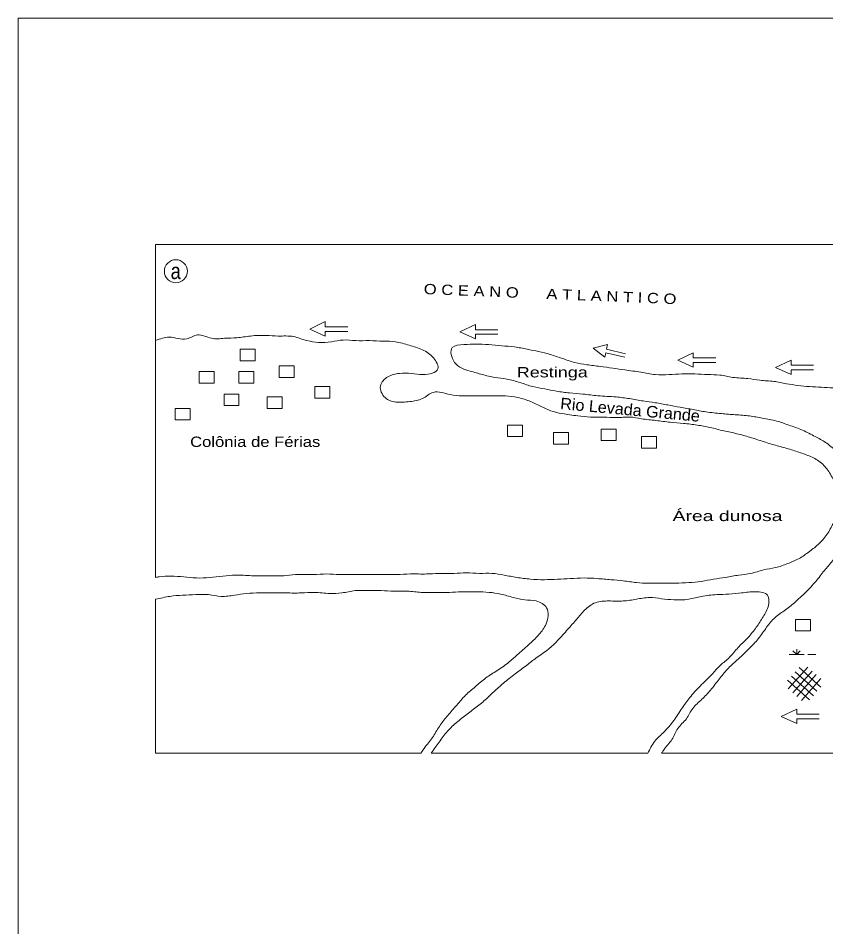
# Model space of a CAD drawing. Extents: x -4.1 to 18.6, y -18.7 to 13.4.
# Drawn here: x -4.12 to 9.93, y -2.41 to 13.4 of the extents above; entities that cross this region are included whole.
import ezdxf
from ezdxf.enums import TextEntityAlignment as Align

# ---------------------------------------------------------------- set-up
doc = ezdxf.new("R2010")
doc.units = 0
doc.header["$LTSCALE"] = 0.072
doc.layers.add('1', color=7, linetype='Continuous', lineweight=13)
doc.layers.add('3', color=7, linetype='Continuous', lineweight=13)

msp = doc.modelspace()

# ---------------------------------------------------------------- linework, layer by layer
at = {"layer": '1'}
for p, q in [((-1.73, 8.24), (-1.73, 7.79)), ((9.27, 1.73), (9.61, 2.11)), ((9.84, 1.76), (9.46, 2.1)), ((9.71, 1.61), (9.33, 1.95)), ((9.35, 1.66), (9.69, 2.04)), ((9.77, 1.69), (9.39, 2.03)), ((9.42, 1.6), (9.76, 1.98)), ((9.5, 1.53), (9.84, 1.91)), ((9.64, 1.54), (9.26, 1.88)), ((3.06, 0.61), (6.83, 0.61))]:
    msp.add_line(p, q, dxfattribs=at)
for points in [[(18.56, -18.67), (18.56, 13.4), (-4.12, 13.4), (-4.12, -18.67)], [(-0.26, 7.64), (0, 7.64), (0, 7.44), (-0.26, 7.44)], [(0.42, 7.35), (0.68, 7.35), (0.68, 7.15), (0.42, 7.15)], [(-0.97, 7.25), (-0.71, 7.25), (-0.71, 7.05), (-0.97, 7.05)], [(-0.28, 7.25), (-0.02, 7.25), (-0.02, 7.05), (-0.28, 7.05)], [(1.04, 6.99), (1.3, 6.99), (1.3, 6.79), (1.04, 6.79)], [(-0.54, 6.86), (-0.28, 6.86), (-0.28, 6.66), (-0.54, 6.66)], [(0.21, 6.81), (0.47, 6.81), (0.47, 6.61), (0.21, 6.61)], [(-1.39, 6.61), (-1.13, 6.61), (-1.13, 6.41), (-1.39, 6.41)], [(4.39, 6.32), (4.65, 6.32), (4.65, 6.12), (4.39, 6.12)], [(5.19, 6.19), (5.45, 6.19), (5.45, 5.99), (5.19, 5.99)], [(6.02, 6.25), (6.28, 6.25), (6.28, 6.05), (6.02, 6.05)], [(6.72, 6.12), (6.98, 6.12), (6.98, 5.92), (6.72, 5.92)], [(9.4, 2.94), (9.66, 2.94), (9.66, 2.74), (9.4, 2.74)]]:
    msp.add_lwpolyline(points, close=True, dxfattribs=at)
for points in [[(12.86, 7.13), (12.86, 9.46), (-1.73, 9.46), (-1.73, 8.24)], [(1.61, 8.03), (1.22, 8.03), (1.22, 8.12), (0.95, 7.99)], [(4.22, 7.98), (3.83, 7.98), (3.83, 8.07), (3.56, 7.94)], [(1.61, 7.95), (1.22, 7.95), (1.22, 7.87), (0.95, 7.99)], [(4.22, 7.9), (3.83, 7.9), (3.83, 7.82), (3.56, 7.94)], [(-1.73, 3.67), (-1.73, 7.54), (-1.73, 7.79)], [(6.44, 7.56), (6.11, 7.64), (6.13, 7.72), (5.88, 7.66)], [(6.43, 7.5), (6.1, 7.58), (6.08, 7.5), (5.88, 7.66)], [(8.01, 7.49), (7.62, 7.49), (7.62, 7.58), (7.35, 7.45)], [(8.01, 7.41), (7.62, 7.41), (7.62, 7.33), (7.35, 7.45)], [(9.71, 7.36), (9.32, 7.36), (9.32, 7.45), (9.05, 7.32)], [(9.71, 7.28), (9.32, 7.28), (9.32, 7.2), (9.05, 7.32)], [(7.07, 0.61), (12.86, 0.61), (12.86, 4.2)], [(2.88, 0.61), (-1.73, 0.61), (-1.73, 3.29)], [(9.81, 1.29), (9.42, 1.29), (9.42, 1.38), (9.15, 1.25)], [(9.81, 1.21), (9.42, 1.21), (9.42, 1.13), (9.15, 1.25)]]:
    msp.add_lwpolyline(points, dxfattribs=at)
msp.add_circle((-1.378, 8.997), 0.2, dxfattribs=at)
for points in [[(-1.73, 7.79), (-1.49, 7.85), (-1.19, 7.82), (-1, 7.89), (-0.76, 7.83), (-0.53, 7.83), (-0.32, 7.84), (-0.08, 7.87), (0.19, 7.88), (0.4, 7.87), (0.67, 7.86), (0.9, 7.79), (1.1, 7.76), (1.33, 7.77), (1.53, 7.8), (1.75, 7.79), (1.99, 7.79), (2.23, 7.78), (2.44, 7.77), (2.68, 7.71), (2.91, 7.63), (3.1, 7.49), (3.18, 7.3), (2.92, 7.2), (2.72, 7.22), (2.51, 7.22), (2.31, 7.16), (2.18, 7), (2.26, 6.8), (2.45, 6.72), (2.69, 6.73), (2.91, 6.78), (3.1, 6.89), (3.39, 6.85), (3.6, 6.83), (3.84, 6.83), (4.08, 6.83), (4.3, 6.83), (4.51, 6.81), (4.74, 6.75), (4.94, 6.66), (5.14, 6.57), (5.34, 6.52), (5.61, 6.48), (5.83, 6.46), (6.06, 6.46), (6.28, 6.45), (6.52, 6.46), (6.72, 6.43), (6.97, 6.4), (7.22, 6.37), (7.45, 6.35), (7.69, 6.32), (7.91, 6.28), (8.15, 6.22), (8.38, 6.17), (8.6, 6.11), (8.85, 6.03), (9.08, 5.96), (9.3, 5.9), (9.51, 5.83), (9.71, 5.75), (9.89, 5.62), (10.02, 5.44), (10.12, 5.25), (10.16, 5.05), (10.16, 4.84), (10.07, 4.64), (9.96, 4.44), (9.81, 4.26), (9.64, 4.12), (9.46, 4), (9.26, 3.91), (9.05, 3.84), (8.84, 3.8), (8.62, 3.74), (8.41, 3.71), (8.18, 3.67), (7.97, 3.64), (7.76, 3.6), (7.54, 3.58), (7.31, 3.57), (7.08, 3.57), (6.85, 3.57), (6.63, 3.58), (6.4, 3.61), (6.19, 3.63), (5.95, 3.65), (5.72, 3.66), (5.48, 3.65), (5.26, 3.64)], [(-1.73, 7.79), (-1.49, 7.85), (-1.19, 7.82), (-1, 7.89), (-0.76, 7.83), (-0.53, 7.83), (-0.32, 7.84), (-0.08, 7.87), (0.19, 7.88), (0.4, 7.87), (0.67, 7.86), (0.9, 7.79), (1.1, 7.76), (1.33, 7.77), (1.53, 7.8), (1.75, 7.79), (1.99, 7.79), (2.23, 7.78), (2.44, 7.77), (2.68, 7.71), (2.91, 7.63), (3.1, 7.49), (3.18, 7.3), (2.92, 7.2), (2.72, 7.22), (2.51, 7.22), (2.31, 7.16), (2.18, 7), (2.26, 6.8), (2.45, 6.72), (2.69, 6.73), (2.91, 6.78), (3.1, 6.89), (3.39, 6.85), (3.6, 6.83), (3.84, 6.83), (4.08, 6.83), (4.3, 6.83), (4.51, 6.81), (4.74, 6.75), (4.94, 6.66), (5.14, 6.57), (5.34, 6.52), (5.61, 6.48), (5.83, 6.46), (6.06, 6.46), (6.28, 6.45), (6.52, 6.46), (6.72, 6.43), (6.97, 6.4), (7.22, 6.37), (7.45, 6.35), (7.69, 6.32), (7.91, 6.28), (8.15, 6.22), (8.38, 6.17), (8.6, 6.11), (8.85, 6.03), (9.08, 5.96), (9.3, 5.9), (9.51, 5.83), (9.71, 5.75), (9.89, 5.62), (10.02, 5.44), (10.12, 5.25), (10.16, 5.05), (10.16, 4.84), (10.07, 4.64), (9.96, 4.44), (9.81, 4.26), (9.64, 4.12), (9.46, 4), (9.26, 3.91), (9.05, 3.84), (8.84, 3.8), (8.62, 3.74), (8.41, 3.71), (8.18, 3.67), (7.97, 3.64), (7.76, 3.6), (7.54, 3.58), (7.31, 3.57), (7.08, 3.57), (6.85, 3.57), (6.63, 3.58), (6.4, 3.61), (6.19, 3.63), (5.95, 3.65), (5.72, 3.66), (5.48, 3.65), (5.26, 3.64)], [(-1.73, 7.79), (-1.49, 7.85), (-1.19, 7.82), (-1, 7.89), (-0.76, 7.83), (-0.53, 7.83), (-0.32, 7.84), (-0.08, 7.87), (0.19, 7.88), (0.4, 7.87), (0.67, 7.86), (0.9, 7.79), (1.1, 7.76), (1.33, 7.77), (1.53, 7.8), (1.75, 7.79), (1.99, 7.79), (2.23, 7.78), (2.44, 7.77), (2.68, 7.71), (2.91, 7.63), (3.1, 7.49), (3.18, 7.3), (2.92, 7.2), (2.72, 7.22), (2.51, 7.22), (2.31, 7.16), (2.18, 7), (2.26, 6.8), (2.45, 6.72), (2.69, 6.73), (2.91, 6.78), (3.1, 6.89), (3.39, 6.85), (3.6, 6.83), (3.84, 6.83), (4.08, 6.83), (4.3, 6.83), (4.51, 6.81), (4.74, 6.75), (4.94, 6.66), (5.14, 6.57), (5.34, 6.52), (5.61, 6.48), (5.83, 6.46), (6.06, 6.46), (6.28, 6.45), (6.52, 6.46), (6.72, 6.43), (6.97, 6.4), (7.22, 6.37), (7.45, 6.35), (7.69, 6.32), (7.91, 6.28), (8.15, 6.22), (8.38, 6.17), (8.6, 6.11), (8.85, 6.03), (9.08, 5.96), (9.3, 5.9), (9.51, 5.83), (9.71, 5.75), (9.89, 5.62), (10.02, 5.44), (10.12, 5.25), (10.16, 5.05), (10.16, 4.84), (10.07, 4.64), (9.96, 4.44), (9.81, 4.26), (9.64, 4.12), (9.46, 4), (9.26, 3.91), (9.05, 3.84), (8.84, 3.8), (8.62, 3.74), (8.41, 3.71), (8.18, 3.67), (7.97, 3.64), (7.76, 3.6), (7.54, 3.58), (7.31, 3.57), (7.08, 3.57), (6.85, 3.57), (6.63, 3.58), (6.4, 3.61), (6.19, 3.63), (5.95, 3.65), (5.72, 3.66), (5.48, 3.65), (5.26, 3.64)], [(12.86, 7.1), (12.66, 7), (12.46, 7.1), (12.26, 7.06), (11.95, 7.06), (11.75, 7.03), (11.54, 7.06), (11.33, 7.04), (11.12, 7.1), (10.9, 7.06), (10.7, 7.02), (10.47, 7.01), (10.26, 6.99), (10.05, 6.97), (9.85, 6.98), (9.64, 6.99), (9.44, 7.01), (9.24, 7.04), (9.02, 7.08), (8.78, 7.1), (8.57, 7.13), (8.31, 7.15), (8.08, 7.19), (7.87, 7.2), (7.65, 7.21), (7.42, 7.21), (7.2, 7.2), (6.96, 7.2), (6.71, 7.24), (6.43, 7.28), (6.22, 7.31), (6, 7.34), (5.77, 7.37), (5.56, 7.41), (5.34, 7.48), (5.13, 7.55), (4.93, 7.6), (4.73, 7.64), (4.51, 7.68), (4.29, 7.7), (4.06, 7.72), (3.84, 7.73), (3.63, 7.72), (3.43, 7.67), (3.47, 7.41), (3.74, 7.26), (3.95, 7.2), (4.17, 7.15), (4.38, 7.12), (4.61, 7.06), (4.83, 6.99), (5.04, 6.95), (5.24, 6.91), (5.47, 6.88), (5.7, 6.86), (5.96, 6.83), (6.28, 6.81), (6.51, 6.78), (6.75, 6.74), (6.96, 6.71), (7.18, 6.67), (7.39, 6.63), (7.62, 6.59), (7.84, 6.55), (8.11, 6.52), (8.35, 6.5), (8.6, 6.48), (8.82, 6.44), (9.07, 6.39), (9.28, 6.32), (9.52, 6.23), (9.74, 6.12), (9.92, 6.02), (10.1, 5.87), (10.26, 5.71), (10.4, 5.55), (10.57, 5.35), (10.75, 5.2), (10.94, 5.09), (11.16, 5.03), (11.35, 4.95), (11.57, 4.87), (11.84, 4.78), (12.02, 4.68), (12.24, 4.6), (12.44, 4.54), (12.64, 4.44), (12.83, 4.34), (12.86, 4.31)], [(12.86, 4.31), (12.83, 4.34), (12.64, 4.44), (12.44, 4.54), (12.24, 4.6), (12.02, 4.68), (11.84, 4.78), (11.57, 4.87), (11.35, 4.95), (11.16, 5.03), (10.94, 5.09), (10.75, 5.2), (10.57, 5.35), (10.4, 5.55), (10.26, 5.71), (10.1, 5.87), (9.92, 6.02), (9.74, 6.12), (9.52, 6.23), (9.28, 6.32), (9.07, 6.39), (8.82, 6.44), (8.6, 6.48), (8.35, 6.5), (8.11, 6.52), (7.84, 6.55), (7.62, 6.59), (7.39, 6.63), (7.18, 6.67), (6.96, 6.71), (6.75, 6.74), (6.51, 6.78), (6.28, 6.81), (5.96, 6.83), (5.7, 6.86), (5.47, 6.88), (5.24, 6.91), (5.04, 6.95), (4.83, 6.99), (4.61, 7.06), (4.38, 7.12), (4.17, 7.15), (3.95, 7.2), (3.74, 7.26), (3.47, 7.41), (3.43, 7.67), (3.63, 7.72), (3.84, 7.73), (4.06, 7.72), (4.29, 7.7), (4.51, 7.68), (4.73, 7.64), (4.93, 7.6), (5.13, 7.55), (5.34, 7.48), (5.56, 7.41), (5.77, 7.37), (6, 7.34), (6.22, 7.31), (6.43, 7.28), (6.71, 7.24), (6.96, 7.2), (7.2, 7.2), (7.42, 7.21), (7.65, 7.21), (7.87, 7.2), (8.08, 7.19), (8.31, 7.15), (8.57, 7.13), (8.78, 7.1), (9.02, 7.08), (9.24, 7.04), (9.44, 7.01), (9.64, 6.99), (9.85, 6.98), (10.05, 6.97), (10.26, 6.99), (10.47, 7.01), (10.7, 7.02), (10.9, 7.06), (11.12, 7.1), (11.33, 7.04), (11.54, 7.06), (11.75, 7.03), (11.95, 7.06), (12.26, 7.06), (12.46, 7.1), (12.66, 7), (12.86, 7.1)], [(12.86, 4.2), (12.64, 4.31), (12.44, 4.4), (12.24, 4.48), (12.05, 4.57), (11.83, 4.64), (11.6, 4.69), (11.35, 4.77), (11.15, 4.84), (10.95, 4.85), (10.7, 4.83), (10.55, 4.69), (10.43, 4.51), (10.3, 4.33), (10.16, 4.14), (10.04, 3.96), (9.9, 3.79), (9.75, 3.6), (9.57, 3.41), (9.38, 3.23), (9.2, 3.09), (9.02, 2.95), (8.88, 2.78), (8.73, 2.58), (8.57, 2.41), (8.38, 2.23), (8.21, 2.07), (8.07, 1.9), (7.92, 1.71), (7.77, 1.55), (7.61, 1.39), (7.5, 1.21), (7.35, 1.04), (7.25, 0.85), (7.1, 0.66), (7.07, 0.61)], [(7.07, 0.61), (7.1, 0.66), (7.25, 0.85), (7.35, 1.04), (7.5, 1.21), (7.61, 1.39), (7.77, 1.55), (7.92, 1.71), (8.07, 1.9), (8.21, 2.07), (8.38, 2.23), (8.57, 2.41), (8.73, 2.58), (8.88, 2.78), (9.02, 2.95), (9.2, 3.09), (9.38, 3.23), (9.57, 3.41), (9.75, 3.6), (9.9, 3.79), (10.04, 3.96), (10.16, 4.14), (10.3, 4.33), (10.43, 4.51), (10.55, 4.69), (10.7, 4.83), (10.95, 4.85), (11.15, 4.84), (11.35, 4.77), (11.6, 4.69), (11.83, 4.64), (12.05, 4.57), (12.24, 4.48), (12.44, 4.4), (12.64, 4.31), (12.86, 4.2)], [(5.26, 3.64), (5.03, 3.63), (4.79, 3.64), (4.55, 3.67), (4.33, 3.71), (4.12, 3.74), (3.9, 3.74), (3.67, 3.75), (3.46, 3.74), (3.19, 3.74), (2.98, 3.73), (2.7, 3.73), (2.46, 3.72), (2.23, 3.72), (2.01, 3.72), (1.7, 3.72), (1.46, 3.72), (1.25, 3.73), (1.01, 3.72), (0.7, 3.72), (0.5, 3.7), (0.26, 3.7), (-0.06, 3.7), (-0.34, 3.71), (-0.56, 3.69), (-0.79, 3.67), (-1.02, 3.66), (-1.24, 3.68), (-1.46, 3.69), (-1.67, 3.68), (-1.73, 3.67)], [(5.26, 3.64), (5.03, 3.63), (4.79, 3.64), (4.55, 3.67), (4.33, 3.71), (4.12, 3.74), (3.9, 3.74), (3.67, 3.75), (3.46, 3.74), (3.19, 3.74), (2.98, 3.73), (2.7, 3.73), (2.46, 3.72), (2.23, 3.72), (2.01, 3.72), (1.7, 3.72), (1.46, 3.72), (1.25, 3.73), (1.01, 3.72), (0.7, 3.72), (0.5, 3.7), (0.26, 3.7), (-0.06, 3.7), (-0.34, 3.71), (-0.56, 3.69), (-0.79, 3.67), (-1.02, 3.66), (-1.24, 3.68), (-1.46, 3.69), (-1.67, 3.68), (-1.73, 3.67)], [(5.26, 3.64), (5.03, 3.63), (4.79, 3.64), (4.55, 3.67), (4.33, 3.71), (4.12, 3.74), (3.9, 3.74), (3.67, 3.75), (3.46, 3.74), (3.19, 3.74), (2.98, 3.73), (2.7, 3.73), (2.46, 3.72), (2.23, 3.72), (2.01, 3.72), (1.7, 3.72), (1.46, 3.72), (1.25, 3.73), (1.01, 3.72), (0.7, 3.72), (0.5, 3.7), (0.26, 3.7), (-0.06, 3.7), (-0.34, 3.71), (-0.56, 3.69), (-0.79, 3.67), (-1.02, 3.66), (-1.24, 3.68), (-1.46, 3.69), (-1.67, 3.68), (-1.73, 3.67)], [(-1.73, 3.29), (-1.48, 3.34), (-1.26, 3.36), (-1.03, 3.37), (-0.81, 3.37), (-0.59, 3.34), (-0.36, 3.36), (-0.15, 3.39), (0.08, 3.4), (0.32, 3.4), (0.54, 3.4), (0.8, 3.4), (1.03, 3.41), (1.3, 3.39), (1.51, 3.4), (1.74, 3.44), (1.96, 3.44), (2.19, 3.44), (2.42, 3.43), (2.65, 3.43), (2.89, 3.41), (3.14, 3.41), (3.38, 3.41), (3.59, 3.42), (3.85, 3.42), (4.07, 3.41), (4.27, 3.38), (4.49, 3.32), (4.69, 3.28), (4.89, 3.26), (5.07, 3.14), (5.06, 2.86), (4.94, 2.68), (4.78, 2.52), (4.58, 2.34), (4.42, 2.2), (4.21, 2.05), (4.01, 1.92), (3.83, 1.77), (3.66, 1.62), (3.51, 1.45), (3.35, 1.27), (3.22, 1.1), (3.1, 0.91), (2.96, 0.72), (2.88, 0.61)], [(-1.73, 3.29), (-1.48, 3.34), (-1.26, 3.36), (-1.03, 3.37), (-0.81, 3.37), (-0.59, 3.34), (-0.36, 3.36), (-0.15, 3.39), (0.08, 3.4), (0.32, 3.4), (0.54, 3.4), (0.8, 3.4), (1.03, 3.41), (1.3, 3.39), (1.51, 3.4), (1.74, 3.44), (1.96, 3.44), (2.19, 3.44), (2.42, 3.43), (2.65, 3.43), (2.89, 3.41), (3.14, 3.41), (3.38, 3.41), (3.59, 3.42), (3.85, 3.42), (4.07, 3.41), (4.27, 3.38), (4.49, 3.32), (4.69, 3.28), (4.89, 3.26), (5.07, 3.14), (5.06, 2.86), (4.94, 2.68), (4.78, 2.52), (4.58, 2.34), (4.42, 2.2), (4.21, 2.05), (4.01, 1.92), (3.83, 1.77), (3.66, 1.62), (3.51, 1.45), (3.35, 1.27), (3.22, 1.1), (3.1, 0.91), (2.96, 0.72), (2.88, 0.61)], [(6.83, 0.61), (6.95, 0.82), (7.11, 0.98), (7.28, 1.18), (7.42, 1.39), (7.56, 1.58), (7.74, 1.78), (7.94, 1.98), (8.09, 2.14), (8.25, 2.28), (8.4, 2.45), (8.55, 2.6), (8.7, 2.78), (8.82, 2.96), (8.92, 3.16), (8.91, 3.36), (8.71, 3.42), (8.46, 3.4), (8.24, 3.38), (8.03, 3.37), (7.76, 3.34), (7.54, 3.29), (7.28, 3.28), (7.07, 3.3), (6.86, 3.32), (6.63, 3.29), (6.4, 3.26), (6.15, 3.26), (5.92, 3.23), (5.73, 3.1), (5.59, 2.94), (5.44, 2.77), (5.26, 2.57), (5.1, 2.42), (4.89, 2.27), (4.72, 2.14), (4.52, 1.99), (4.32, 1.83), (4.15, 1.68), (3.98, 1.52), (3.8, 1.38), (3.62, 1.24), (3.43, 1.08), (3.27, 0.9), (3.13, 0.71), (3.06, 0.61)], [(3.06, 0.61), (3.13, 0.71), (3.27, 0.9), (3.43, 1.08), (3.62, 1.24), (3.8, 1.38), (3.98, 1.52), (4.15, 1.68), (4.32, 1.83), (4.52, 1.99), (4.72, 2.14), (4.89, 2.27), (5.1, 2.42), (5.26, 2.57), (5.44, 2.77), (5.59, 2.94), (5.73, 3.1), (5.92, 3.23), (6.15, 3.26), (6.4, 3.26), (6.63, 3.29), (6.86, 3.32), (7.07, 3.3), (7.28, 3.28), (7.54, 3.29), (7.76, 3.34), (8.03, 3.37), (8.24, 3.38), (8.46, 3.4), (8.71, 3.42), (8.91, 3.36), (8.92, 3.16), (8.82, 2.96), (8.7, 2.78), (8.55, 2.6), (8.4, 2.45), (8.25, 2.28), (8.09, 2.14), (7.94, 1.98), (7.74, 1.78), (7.56, 1.58), (7.42, 1.39), (7.28, 1.18), (7.11, 0.98), (6.95, 0.82), (6.83, 0.61)]]:
    msp.add_spline(points, degree=3, dxfattribs=at)
at = {"layer": '3'}
for p, q in [((9.42, 2.33), (9.35, 2.39)), ((9.42, 2.33), (9.42, 2.42)), ((9.42, 2.33), (9.48, 2.39)), ((9.29, 2.33), (9.55, 2.33)), ((9.61, 2.33), (9.75, 2.33))]:
    msp.add_line(p, q, dxfattribs=at)

# ---------------------------------------------------------------- texts
at = {"layer": '1', "width": 0.85}
msp.add_text('a', height=0.28, dxfattribs=at).set_placement((-1.38, 8.86), align=Align.CENTER)
at = {"layer": '1'}
for s, height, rotation, width, p in [('O C E A N O      A T L A N T I C O ', 0.18, 357.705, 1.2, (2.93, 8.6)), ('Rio Levada Grande', 0.2, 354.757, 1.05, (5.3, 6.6))]:
    msp.add_text(s, height=height, rotation=rotation, dxfattribs=dict(at, width=width)).set_placement(p)
for s, width, p in [('Restinga', 1.3, (4.55, 7.15)), ('Colônia de Férias', 1.2, (-1.13, 5.94)), ('Área dunosa', 1.4, (7.26, 4.65))]:
    msp.add_text(s, height=0.18, dxfattribs=dict(at, width=width)).set_placement(p)

doc.saveas('drawing.dxf')
